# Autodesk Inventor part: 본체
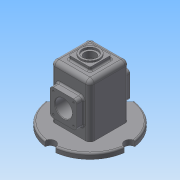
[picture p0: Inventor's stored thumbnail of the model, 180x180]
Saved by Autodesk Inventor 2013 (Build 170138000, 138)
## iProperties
Created: 2018-07
Part Number: 본체
Material: 일반
Document SubType Name: Modeling
Designer: Administrator
Density: 1 g/cm^3
Author: Administrator
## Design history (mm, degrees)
sketch "스케치1"
  geometry: L1 (37, 37)-(-37, 37); L2 (-37, 37)-(-37, -37); L3 (-37, -37)-(37, -37); L4 (37, -37)-(37, 37); L5 (37, 37)-(-37, -37); L6 (-37, 37)-(37, -37); 3 further points
  constraints: 12 end point, 3 midpoint, 2 parallel, 1 coincident, 1 horizontal, 1 perpendicular
  dimensions: "d0" = 74 distance of L3.end L2.end; "d1" = 74 distance of L2.end L1.end
extrude "돌출1" new body sketch "스케치1" stored distance "d2" = 110; taper "d3" = 0 deg
fillet "모깎기1" dims "d4" = 8
fillet "모깎기2" dims "d5" = 8
feature "쉘1" dims "d6" = 5
node "작업 평면1"
sketch "스케치3"
  geometry: L1 (-25, -25)-(25, -25); L2 (25, -25)-(25, 25); L3 (25, 25)-(-25, 25); L4 (-25, 25)-(-25, -25); L5 (-25, -25)-(25, 25); L6 (25, -25)-(-25, 25); L7 (29, -55)-(-29, -55) reference; 3 further points
  constraints: 12 end point, 3 midpoint, 2 parallel, 1 coincident, 1 horizontal, 1 perpendicular
  dimensions: "d11" = 50 distance of L3.end L2.end; "d12" = 50 distance of L2.end L1.end; "d13" = 55 distance from line of L7 point (0, 0)
extrude "돌출2" join sketch "스케치3" distance "d14" = 100; taper "d15" = 0 deg
sketch "스케치4"
  geometry: L1 (-32, -29)-(-32, 29) reference; L2 (-29, 32)-(29, 32) reference; L3 (32, 29)-(32, -29) reference; L4 (29, -32)-(-29, -32) reference; L5 (-29, -32)-(29, -32); L6 (32, -29)-(32, 29); L7 (29, 32)-(-29, 32); L8 (-32, 29)-(-32, -29); A1 r 3 centre (-29, -29) between (-32, -29) and (-29, -32) reference; A2 r 3 centre (-29, 29) between (-29, 32) and (-32, 29) reference; A3 r 3 centre (29, 29) between (32, 29) and (29, 32) reference; A4 r 3 centre (29, -29) between (29, -32) and (32, -29) reference; A5 r 3 centre (-29, 29) between (-29, 32) and (-32, 29); A6 r 3 centre (29, 29) between (32, 29) and (29, 32); A7 r 3 centre (29, -29) between (29, -32) and (32, -29); A8 r 3 centre (-29, -29) between (-32, -29) and (-29, -32); 1 further point
  constraints: 8 end point, 8 point on circle, 8 tangent, 4 centre point, 4 collinear, 3 equal radius, 2 parallel, 1 horizontal, 1 perpendicular
  dimensions: "d16" = 3 radius of A5
extrude "돌출3" cut sketch "스케치4" distance "d17" = 85; taper "d18" = 0 deg
sketch "스케치5"
  geometry: C1 r 25 at (29, -47); 1 further point
  constraints: 1 centre point, 1 coincident
  dimensions: "d19" = 50 diameter of C1
extrude "돌출4" join sketch "스케치5" distance "d20" = 7; taper "d21" = -20 deg
sketch "스케치7"
  geometry: C1 r 25 at (29, -47); 1 further point
  constraints: 1 centre point, 1 coincident
  dimensions: "d22" = 50 diameter of C1
extrude "돌출5" join sketch "스케치7" distance "d23" = 7; taper "d24" = -20 deg
sketch "스케치9"
  geometry: C1 r 16 at (0, 0); 1 further point
  constraints: 1 centre point, 1 coincident
  dimensions: "d25" = 32 diameter of C1
extrude "돌출6" cut sketch "스케치9" stored distance "d26" = 7; taper "d27" = 0 deg
sketch "스케치11"
  geometry: L1 (-20, -20)-(20, -20); L2 (20, -20)-(20, 20); L3 (20, 20)-(-20, 20); L4 (-20, 20)-(-20, -20); L5 (-20, -20)-(20, 20); L6 (20, -20)-(-20, 20); 1 further point
  constraints: 12 end point, 2 midpoint, 2 parallel, 1 horizontal, 1 perpendicular
  dimensions: "d28" = 40 distance of L3.end L2.end; "d29" = 40 distance of L2.end L1.end
extrude "돌출7" join sketch "스케치11" distance "d30" = 7; taper "d31" = 0 deg
sketch "스케치12"
  geometry: C1 r 17.5 at (0, 0); 1 further point
  constraints: 1 centre point, 1 coincident
  dimensions: "d32" = 35 diameter of C1
extrude "돌출8" join sketch "스케치12" distance "d34" = 3; taper "d35" = 0 deg
sketch "스케치13"
  geometry: C1 r 17.5 at (0, 0) reference; 1 further point
  constraints: 1 coincident
hole "구멍1" sketch "스케치13" at (0, 0) diameter "d36" = 21; stored, may be unused: countersink angle "d40" = 90 deg, drill point angle "d42" = 0 deg; dims "d37" = 6, "d38" = 28, "d39" = 4, "d41" = 21
sketch "스케치14"
  geometry: L1 (-29, -37)-(29, -37) reference; L2 (37, -29)-(37, 29) reference; L3 (29, 37)-(-29, 37) reference; L4 (-37, 29)-(-37, -29) reference; C1 r 75 at (0, 0); A1 r 8 centre (-29, -29) between (-37, -29) and (-29, -37) reference; A2 r 8 centre (29, -29) between (29, -37) and (37, -29) reference; A3 r 8 centre (29, 29) between (37, 29) and (29, 37) reference; A4 r 8 centre (-29, 29) between (-29, 37) and (-37, 29) reference; 1 further point
  constraints: 1 centre point, 1 coincident
  dimensions: "d43" = 150 diameter of C1
extrude "돌출9" join sketch "스케치14" distance "d44" = 10; taper "d45" = 0 deg
sketch "스케치15"
  geometry: C1 r 10 at (0, 75); C2 r 10 at (75, 0); C3 r 10 at (0, -75); C4 r 10 at (-75, 0); C5 r 75 at (0, 0); A1 r 75 centre (0, 0) between (0, 75) and (-75, 0) reference
  constraints: 5 centre point, 4 point on circle, 3 equal radius, 2 horizontal alignment, 2 vertical alignment, 1 coincident
  dimensions: "d46" = 20 diameter of C1; "d47" = 150 diameter of C5
extrude "돌출10" cut sketch "스케치15" stored distance "d48" = 10; taper "d49" = 0 deg
fillet "모깎기3" dims "d50" = 6
sketch "스케치16"
  geometry: A1 r 6 centre (19, -19) between (19, -25) and (25, -19) reference; A2 r 6 centre (19, 19) between (25, 19) and (19, 25) reference; A3 r 6 centre (-19, 19) between (-19, 25) and (-25, 19) reference; A4 r 6 centre (-19, -19) between (-25, -19) and (-19, -25) reference; 4 further points
  constraints: 4 coincident
hole "구멍2" sketch "스케치16" at (-19, 19), (19, 19), (19, -19), (-19, -19) diameter "d51" = 3.242; stored, may be unused: countersink angle "d55" = 90 deg, drill point angle "d57" = 120 deg; dims "d52" = 8, "d53" = 28, "d54" = 4, "d56" = 10
chamfer "모따기1" distance "d58" = 1; stored, may be unused: second distance "d59" = 2, angle "d60" = 45 deg
fillet "모깎기4" dims "d61" = 3
fillet "모깎기5" dims "d62" = 3
fillet "모깎기6" dims "d63" = 3
sketch "스케치17"
  geometry: L1 (66, -92)-(66, 0) reference; L2 (46.5, 18)-(11.5, 18) reference; 2 further points
  constraints: 1 other
  dimensions: "d64" = 37 distance from line of point (29, -12) L1; "d65" = 30 distance from line of point (29, -12) L2
feature "엠보싱1" sketch "스케치17" dims "d0" = 74, "d1" = 74, "d66" = 0.5, "d67" = 0
node "솔리드1"
mirror "대칭2"
